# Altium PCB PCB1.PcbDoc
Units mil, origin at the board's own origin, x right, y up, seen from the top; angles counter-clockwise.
Board outline 6000 x 4000 mil, 2 copper layers (Top Layer, Bottom Layer); 11 components, 17 nets, 146 pads, 0 vias.
Unrouted connection lines stored in the file: 36.
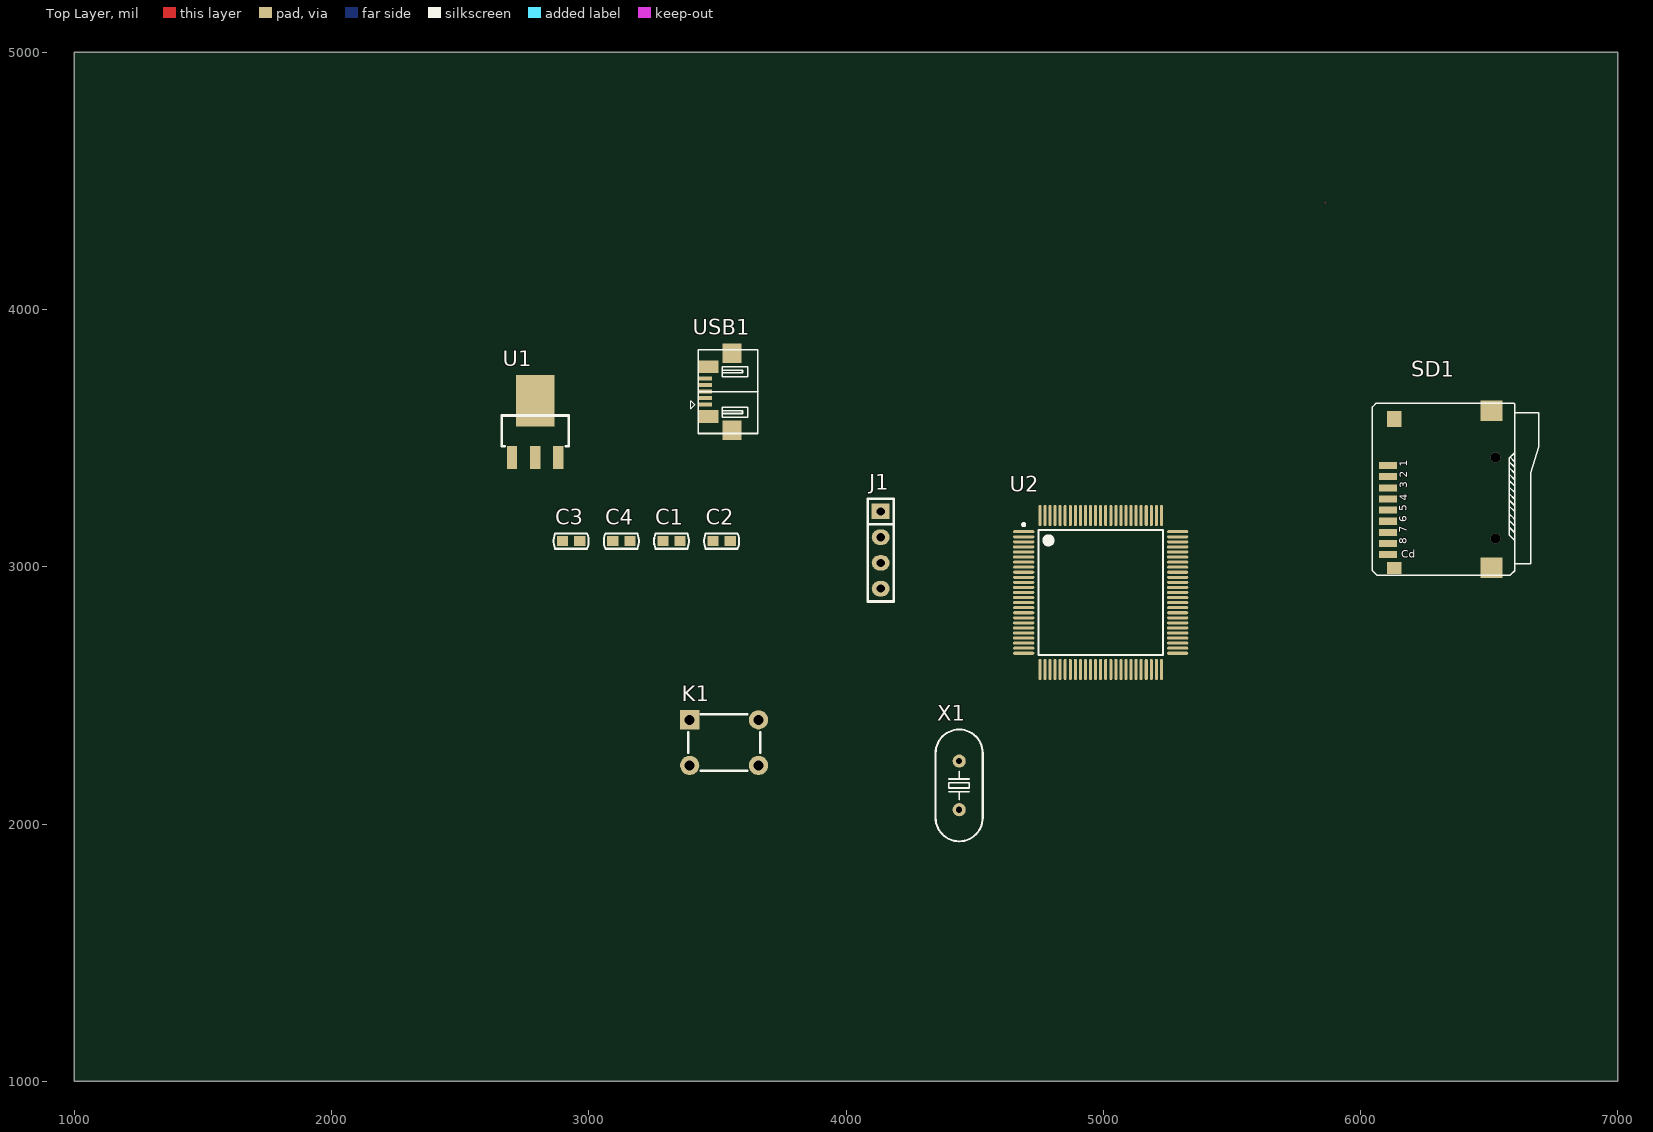
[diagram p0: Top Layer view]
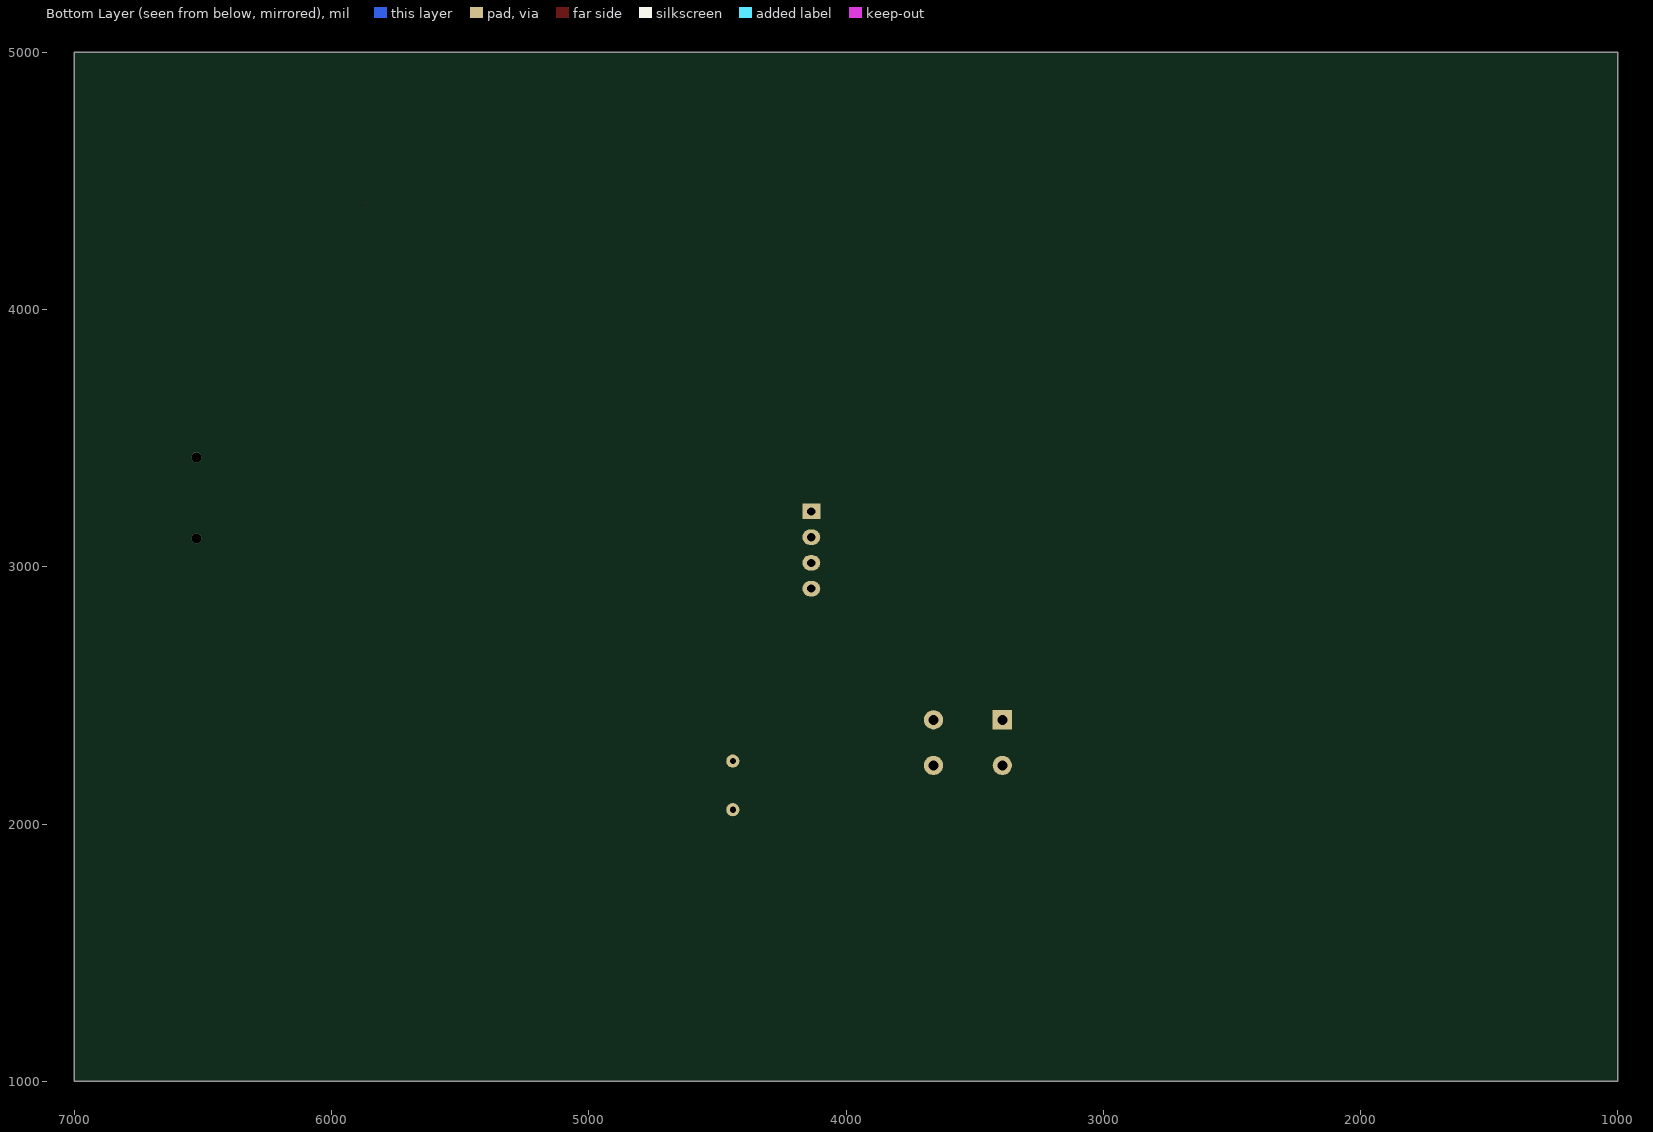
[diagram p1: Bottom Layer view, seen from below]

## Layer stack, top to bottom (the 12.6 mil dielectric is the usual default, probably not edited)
Top Solder: solder mask 0.4, Solder Resist, Dk 3.5
Top Layer: signal copper 1.4
Dielectric 1: dielectric 12.6, FR-4, Dk 4.8
Bottom Layer: signal copper 1.4
Bottom Solder: solder mask 0.4, Solder Resist, Dk 3.5

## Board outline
1000,1000 7000,1000 7000,5000 1000,5000

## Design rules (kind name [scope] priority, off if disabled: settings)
Clearance [All] p1: gap=8 ignorepadtopadclearanceinfootprint=FALSE
PolygonConnect [All] p1: connectstyle=Relief reliefconductorwidth=10 reliefentries=4 polygonreliefangle="90 Angle" airgapwidth=10
RoutingVias [All] p1: holewidth=28 width=50 viastyle="Through Hole" minholewidth=28 minwidth=50 maxholewidth=28 maxwidth=50
SolderMaskExpansion [All] p1: expansion=4
Width [All] p1: maxlimit=10 minlimit=10 preferedwidth=10
30 further rules are at their usual default settings.

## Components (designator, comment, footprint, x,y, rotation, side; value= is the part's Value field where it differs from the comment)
C1 "Cap" C-RAD-0603 3321.54,3100 r0 top value=10uF
C2 "Cap" C-RAD-0603 3516.54,3100 r0 top value=0.1uF
C3 "Cap" C-RAD-0603 2931.54,3100 r0 top value=0.1uF
C4 "Cap" C-RAD-0603 3126.54,3100 r0 top value=10uF
J1 "SWD" "Pin HDR1X4/2.54mm-S" 4135,3215 r0 top
K1 "KEY" DIP-6X6X6 3392.28,2405 r0 top
SD1 "MicroSD" "Micro SD" 6509.25,2995.87 r90 top
U1 "AMS1117_3v3" SOT223 2791.54,3425 r0 top
U2 "STM32F407V" LQFP-100_M 4990,2900 r0 top
USB1 "Micro-USB" USB-MICRO_A 3451.54,3630 r90 top
X1 "8M" "OSC HC-49S" 4440,2150 r90 top

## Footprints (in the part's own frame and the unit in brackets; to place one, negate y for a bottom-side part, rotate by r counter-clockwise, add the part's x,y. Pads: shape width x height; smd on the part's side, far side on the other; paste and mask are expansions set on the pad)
C-RAD-0603 [mm] "贴片电容"
  rect 1.1x1 smd: 1(-0.85,0) 2(0.85,0)
  silkscreen extent -1.73,-0.76 1.73,0.76, body extent -1.14,-0.38 1.14,0.38, height 1
DIP-6X6X6 [mm]
  rect 1.9x1.9 hole 1: 1(0,0)
  round 1.9 hole 1: 2(0,-4.5) 3(6.8,-4.5) 4(6.8,0)
  silkscreen extent -0.16,-5.04 6.96,0.54, body extent -0.68,-5.24 7.53,0.76, height 5.95
LQFP-100_M [mm] "Thin QFP, 100"
  oval 2.1x0.3 smd: 1(-7.6,6) 2(-7.6,5.5) 3(-7.6,5) 4(-7.6,4.5) 5(-7.6,4) 6(-7.6,3.5) 7(-7.6,3) 8(-7.6,2.5) 9(-7.6,2) 10(-7.6,1.5) 11(-7.6,1) 12(-7.6,0.5) 13(-7.6,0) 14(-7.6,-0.5) 15(-7.6,-1) 16(-7.6,-1.5) 17(-7.6,-2) 18(-7.6,-2.5) 19(-7.6,-3) 20(-7.6,-3.5) 21(-7.6,-4) 22(-7.6,-4.5) 23(-7.6,-5) 24(-7.6,-5.5) 25(-7.6,-6) 51(7.6,-6) 52(7.6,-5.5) 53(7.6,-5) 54(7.6,-4.5) 55(7.6,-4) 56(7.6,-3.5) 57(7.6,-3) 58(7.6,-2.5) 59(7.6,-2) 60(7.6,-1.5) 61(7.6,-1) 62(7.6,-0.5) 63(7.6,0) 64(7.6,0.5) 65(7.6,1) 66(7.6,1.5) 67(7.6,2) 68(7.6,2.5) 69(7.6,3) 70(7.6,3.5) 71(7.6,4) 72(7.6,4.5) 73(7.6,5) 74(7.6,5.5) 75(7.6,6)
  oval 0.3x2.1 smd: 26(-6,-7.6) 27(-5.5,-7.6) 28(-5,-7.6) 29(-4.5,-7.6) 30(-4,-7.6) 31(-3.5,-7.6) 32(-3,-7.6) 33(-2.5,-7.6) 34(-2,-7.6) 35(-1.5,-7.6) 36(-1,-7.6) 37(-0.5,-7.6) 38(0,-7.6) 39(0.5,-7.6) 40(1,-7.6) 41(1.5,-7.6) 42(2,-7.6) 43(2.5,-7.6) 44(3,-7.6) 45(3.5,-7.6) 46(4,-7.6) 47(4.5,-7.6) 48(5,-7.6) 49(5.5,-7.6) 50(6,-7.6) 76(6,7.6) 77(5.5,7.6) 78(5,7.6) 79(4.5,7.6) 80(4,7.6) 81(3.5,7.6) 82(3,7.6) 83(2.5,7.6) 84(2,7.6) 85(1.5,7.6) 86(1,7.6) 87(0.5,7.6) 88(0,7.6) 89(-0.5,7.6) 90(-1,7.6) 91(-1.5,7.6) 92(-2,7.6) 93(-2.5,7.6) 94(-3,7.6) 95(-3.5,7.6) 96(-4,7.6) 97(-4.5,7.6) 98(-5,7.6) 99(-5.5,7.6) 100(-6,7.6)
  silkscreen extent -7.72,-6.15 6.15,6.82, body extent -7,-7 7,7, height 0.8
"Micro SD" [mm]
  rect 2.032x2.2 smd: 0(0,0) 0(15.5,0)
  rect 1.2x1.4 smd: 0(0,9.6)
  round 1 hole 1 unplated: 0(2.9,-0.4) 0(10.9,-0.4)
  rect 1.6x1.4 smd: 0(14.7,9.6)
  rect 0.7x1.8 smd: 1(10.1,10.227) 2(9,10.227) 3(7.9,10.227) 4(6.8,10.227) 5(5.7,10.227) 6(4.6,10.227) 7(3.5,10.227) 8(2.4,10.227) 9(1.3,10.227)
  Top Layer lines w0.03: 36.064,16.423 36.114,16.373
  silkscreen extent -0.72,-4.68 16.27,11.75, body extent -0.27,-4.63 16,10.57, height 1.8
"OSC HC-49S" [mm]
  round 1.3 hole 0.6: 1(-2.4,0) 2(2.4,0)
  silkscreen extent -5.52,-2.32 5.52,2.33, body extent -5.53,-2.29 5.53,2.36, height 4.13
"Pin HDR1X4/2.54mm-S" [mil]
  rect 70x60 hole 32: 1(0,0)
  oval 70x60 hole 32: 2(0,-100) 3(0,-200) 4(0,-300)
  silkscreen extent -50,-350 50,50, body extent -50,-350 50,50, height 336
SOT223 [mil]
  rect 40x90 smd: 1(-90,0) 2(0,0) 3(90,0)
  rect 150x200 smd: 2(0,220)
  silkscreen extent -130,43 130,163, body extent -130,-30 126,246, height 65
USB-MICRO_A [mm]
  rect 1.9x1.9 smd: 0(-2.515,-2.667) 0(5.08,-2.667)
  rect 0.4x1.4 smd: 1(0,0) 2(0.648,0) 3(1.295,0) 4(1.943,0) 5(2.591,0)
  rect 1.25x2 smd: 5(-1.168,-0.33) 5(3.759,-0.33)
  silkscreen extent -2.84,-5.24 5.41,1.4, body extent -2.71,-5.08 5.25,0.34, height 2.69

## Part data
C1 C2 C3 C4: "无极性电容"
J1: library part "Pin HDR1X4"
U1: library part AMS1117, "三端稳压芯片"
U2: "STM32单片机100引脚"
X1: library part XTAL-2P, "2脚无源脚晶振"

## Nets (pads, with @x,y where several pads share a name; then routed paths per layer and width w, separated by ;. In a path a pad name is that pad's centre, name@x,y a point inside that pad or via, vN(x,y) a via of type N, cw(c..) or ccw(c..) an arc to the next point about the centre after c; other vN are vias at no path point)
3V3: C3.2 C4.2 J1.1 SD1.4 U1.2
5V: C1.2 C2.2 U1.3 USB1.1
GND: C1.1 C2.1 C3.1 C4.1 J1.4 SD1.0 SD1.6 U1.1 USB1.5
NetK1_1: K1.1 U2.2
NetK1_3: K1.3 U2.38
OSC_8M_IN: U2.12 X1.1
OSC_8M_OUT: U2.13 X1.2
SD_CLK: SD1.5 U2.80
SD_CMD: SD1.3 U2.83
SD_D0: SD1.7 U2.65
SD_D1: SD1.8 U2.66
SD_D2: SD1.1 U2.78
SD_D3: SD1.2 U2.79
SWD_CLK: J1.3 U2.76
SWD_DIO: J1.2 U2.72
上拉下拉: USB1.2 USB1.3
插入识别: SD1.9
pads on no net: K1.2 K1.4 U2.1 U2.3 U2.4 U2.5 U2.6 U2.7 U2.8 U2.9 U2.10 U2.11 U2.14 U2.15 U2.16 U2.17 U2.18 U2.19 U2.20 U2.21 U2.22 U2.23 U2.24 U2.25 U2.26 U2.27 U2.28 U2.29 U2.30 U2.31 U2.32 U2.33 U2.34 U2.35 U2.36 U2.37 U2.39 U2.40 U2.41 U2.42 U2.43 U2.44 U2.45 U2.46 U2.47 U2.48 U2.49 U2.50 U2.51 U2.52 U2.53 U2.54 U2.55 U2.56 U2.57 U2.58 U2.59 U2.60 U2.61 U2.62 U2.63 U2.64 U2.67 U2.68 U2.69 U2.70 U2.71 U2.73 U2.74 U2.75 U2.77 U2.81 U2.82 U2.84 U2.85 U2.86 U2.87 U2.88 U2.89 U2.90 U2.91 U2.92 U2.93 U2.94 U2.95 U2.96 U2.97 U2.98 U2.99 U2.100 USB1.0 USB1.4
